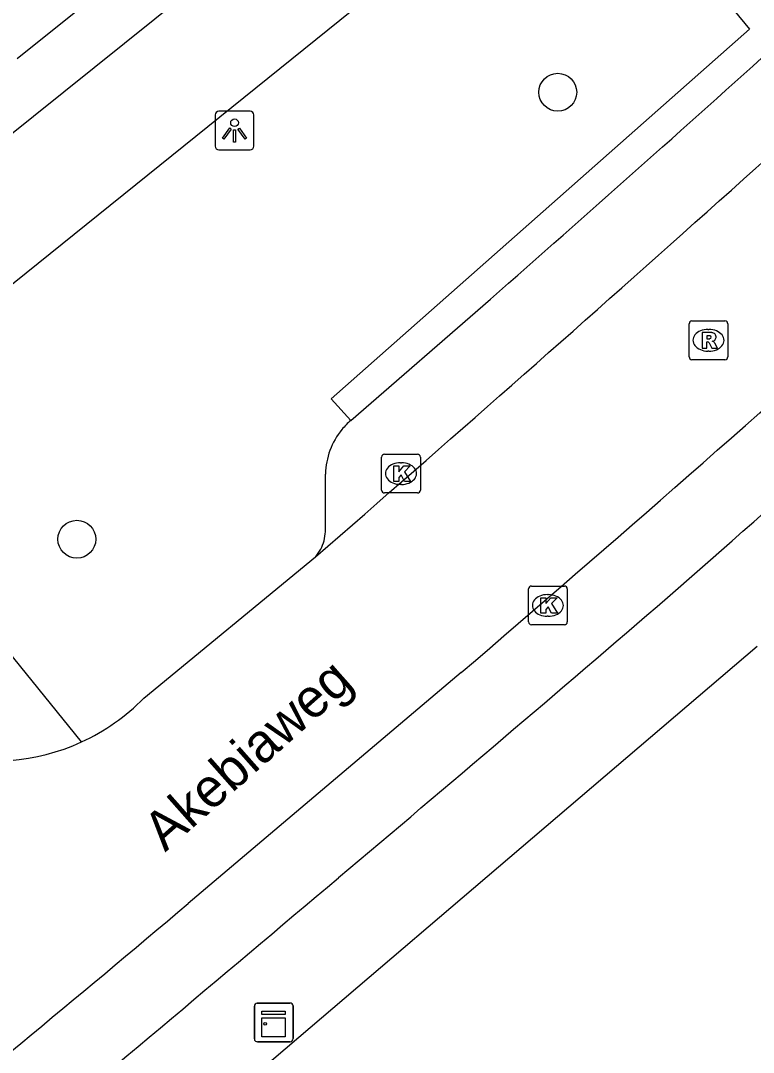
# Model space of a CAD drawing. Extents: x 162347 to 162868, y 381221 to 381813.
# Drawn here: x 162598.22 to 162617.14, y 381573.33 to 381599.97 of the extents above; entities that cross this region are included whole.
import ezdxf

# ---------------------------------------------------------------- set-up
doc = ezdxf.new("R2010")
doc.units = 0
for name, color, linetype in [('IMGEO_Boom', 7, 'Continuous'), ('IMGEO_Kast', 7, 'Continuous'), ('IMGEO_Kolk', 7, 'Continuous'), ('IMGEO_Lichtpunt', 7, 'Continuous'), ('IMGEO_Openbare_ruimte_label', 7, 'Continuous'), ('IMGEO_Pand', 7, 'Continuous'), ('IMGEO_Parkeervlak_open', 7, 'Continuous'), ('IMGEO_Rijbaan_lokaal_open', 7, 'Continuous'), ('IMGEO_Rioolput', 7, 'Continuous'), ('IMGEO_Voetpad_open', 7, 'Continuous')]:
    doc.layers.add(name, color=color, linetype=linetype)

msp = doc.modelspace()

# ---------------------------------------------------------------- linework, layer by layer
at = {"layer": 'IMGEO_Boom'}
for centre in [(162612.089, 381598.119), (162599.676, 381586.577)]:
    msp.add_circle(centre, 0.489, dxfattribs=at)
at = {"layer": 'IMGEO_Kast'}
for p, q in [((162604.257, 381573.675), (162604.257, 381574.516)), ((162604.257, 381574.516), (162604.257, 381573.675)), ((162604.332, 381574.6), (162605.173, 381574.6)), ((162605.173, 381574.6), (162604.332, 381574.6)), ((162605.257, 381574.525), (162605.257, 381573.684)), ((162605.257, 381573.684), (162605.257, 381574.525)), ((162605.182, 381573.6), (162604.341, 381573.6)), ((162604.341, 381573.6), (162605.182, 381573.6))]:
    msp.add_line(p, q, dxfattribs=at)
for points in [[(162604.452, 381574.39), (162605.052, 381574.39), (162605.052, 381574.305), (162604.452, 381574.305), (162604.452, 381574.39)], [(162604.452, 381574.215), (162605.052, 381574.215), (162605.052, 381573.726), (162604.452, 381573.726), (162604.452, 381574.215)]]:
    msp.add_lwpolyline(points, dxfattribs=at)
msp.add_circle((162604.536, 381574.064), 0.0377, dxfattribs=at)
for centre, start, end in [((162604.335, 381574.522), 92.4484, 184.2845), ((162604.335, 381574.522), 92.4484, 184.2845), ((162605.179, 381574.522), 2.4484, 94.2845), ((162605.179, 381574.522), 2.4484, 94.2845), ((162604.335, 381573.678), 182.4484, 274.2845), ((162604.335, 381573.678), 182.4484, 274.2845), ((162605.179, 381573.678), 272.4484, 4.2845), ((162605.179, 381573.678), 272.4484, 4.2845)]:
    msp.add_arc(centre, 0.0779, start, end, dxfattribs=at)
at = {"layer": 'IMGEO_Kolk'}
for p, q in [((162607.541, 381587.846), (162607.541, 381588.698)), ((162607.616, 381588.772), (162608.468, 381588.772)), ((162608.542, 381588.698), (162608.542, 381587.846)), ((162608.029, 381588.552), (162608.054, 381588.552)), ((162608.468, 381587.772), (162607.616, 381587.772)), ((162608.052, 381587.992), (162608.027, 381587.992)), ((162611.409, 381585.367), (162612.261, 381585.367)), ((162611.334, 381584.441), (162611.334, 381585.293)), ((162611.822, 381585.147), (162611.847, 381585.147)), ((162612.335, 381585.293), (162612.335, 381584.441)), ((162611.845, 381584.587), (162611.82, 381584.587)), ((162612.261, 381584.367), (162611.409, 381584.367))]:
    msp.add_line(p, q, dxfattribs=at)
for points in [[(162607.541, 381587.846), (162607.541, 381588.698)], [(162607.616, 381588.772), (162608.468, 381588.772)], [(162608.542, 381588.698), (162608.542, 381587.846)], [(162607.862, 381588.472), (162607.985, 381588.472), (162607.985, 381588.321), (162608.115, 381588.472), (162608.279, 381588.472), (162608.133, 381588.321), (162608.286, 381588.072), (162608.134, 381588.072), (162608.049, 381588.236), (162607.985, 381588.169), (162607.985, 381588.072), (162607.862, 381588.072), (162607.862, 381588.472)], [(162608.468, 381587.772), (162607.616, 381587.772)], [(162611.409, 381585.367), (162612.261, 381585.367)], [(162611.334, 381584.441), (162611.334, 381585.293)], [(162612.335, 381585.293), (162612.335, 381584.441)], [(162611.655, 381585.067), (162611.778, 381585.067), (162611.778, 381584.916), (162611.908, 381585.067), (162612.072, 381585.067), (162611.926, 381584.916), (162612.079, 381584.667), (162611.927, 381584.667), (162611.842, 381584.831), (162611.778, 381584.764), (162611.778, 381584.667), (162611.655, 381584.667), (162611.655, 381585.067)], [(162612.261, 381584.367), (162611.409, 381584.367)]]:
    msp.add_lwpolyline(points, dxfattribs=at)
for centre, start, end in [((162607.618, 381588.696), 91.552, 178.448), ((162607.618, 381588.696), 91.552, 178.448), ((162608.466, 381588.696), 1.552, 88.448), ((162608.466, 381588.696), 1.552, 88.448), ((162607.618, 381587.848), 181.552, 268.448), ((162607.618, 381587.848), 181.552, 268.448), ((162608.466, 381587.848), 271.552, 358.448), ((162608.466, 381587.848), 271.552, 358.448), ((162611.411, 381585.291), 91.552, 178.448), ((162611.411, 381585.291), 91.552, 178.448), ((162612.259, 381585.291), 1.552, 88.448), ((162612.259, 381585.291), 1.552, 88.448), ((162611.411, 381584.443), 181.552, 268.448), ((162611.411, 381584.443), 181.552, 268.448), ((162612.259, 381584.443), 271.552, 358.448), ((162612.259, 381584.443), 271.552, 358.448)]:
    msp.add_arc(centre, 0.0765, start, end, dxfattribs=at)
for centre, major_axis, ratio, start_param, end_param in [((162608.028, 381588.272), (-0.387, 0.002), 0.722429, 4.712389, 7.853982), ((162608.053, 381588.272), (-0.39, 0.002), 0.717154, 1.570796, 4.712389), ((162611.821, 381584.867), (-0.387, 0.002), 0.722429, 4.712389, 7.853982), ((162611.846, 381584.867), (-0.39, 0.002), 0.717154, 1.570796, 4.712389)]:
    msp.add_ellipse(centre, major_axis=major_axis, ratio=ratio, start_param=start_param, end_param=end_param, dxfattribs=at)
at = {"layer": 'IMGEO_Lichtpunt'}
for p, q in [((162604.149, 381597.628), (162603.341, 381597.628)), ((162604.149, 381597.628), (162603.341, 381597.628)), ((162603.247, 381597.533), (162603.247, 381596.726)), ((162603.247, 381597.533), (162603.247, 381596.726)), ((162604.243, 381596.726), (162604.243, 381597.533)), ((162604.243, 381596.726), (162604.243, 381597.533)), ((162603.341, 381596.632), (162604.149, 381596.632)), ((162603.341, 381596.632), (162604.149, 381596.632))]:
    msp.add_line(p, q, dxfattribs=at)
for points in [[(162603.621, 381597.197), (162603.66, 381597.169), (162603.472, 381596.907), (162603.434, 381596.934), (162603.621, 381597.197)], [(162603.723, 381597.149), (162603.77, 381597.149), (162603.77, 381596.827), (162603.723, 381596.827), (162603.723, 381597.149)], [(162603.833, 381597.169), (162603.871, 381597.196), (162604.058, 381596.934), (162604.019, 381596.906), (162603.833, 381597.169)]]:
    msp.add_lwpolyline(points, dxfattribs=at)
msp.add_circle((162603.746, 381597.331), 0.0994, dxfattribs=at)
for centre, start, end in [((162603.341, 381597.533), 90, 180), ((162603.341, 381597.533), 90, 180), ((162604.149, 381597.533), 0, 90), ((162604.149, 381597.533), 0, 90), ((162603.341, 381596.726), 180, 270), ((162603.341, 381596.726), 180, 270), ((162604.149, 381596.726), 270, 0), ((162604.149, 381596.726), 270, 360)]:
    msp.add_arc(centre, 0.0946, start, end, dxfattribs=at)
at = {"layer": 'IMGEO_Pand'}
msp.add_lwpolyline([(162598.133, 381598.994), (162603.15, 381603.02)], dxfattribs=at)
at = {"layer": 'IMGEO_Parkeervlak_open'}
msp.add_lwpolyline([(162606.091, 381586.771), (162606.095, 381588.261)], dxfattribs=at)
for centre, radius, start, end in [((162607.879, 381588.314), 1.747, 130.3263, 141.1491), ((162607.956, 381588.228), 1.862, 140.5909, 178.9871), ((162605.031, 381586.812), 1.061, 332.3969, 357.8036), ((162605.025, 381586.813), 1.067, 319.3854, 332.4487)]:
    msp.add_arc(centre, radius, start, end, dxfattribs=at)
at = {"layer": 'IMGEO_Rijbaan_lokaal_open'}
for points in [[(162601.403, 381582.472), (162605.835, 381586.119)], [(162609.593, 381583.132), (162602.55, 381577.172)]]:
    msp.add_lwpolyline(points, dxfattribs=at)
for centre, radius, start, end in [((161942.339, 382348.939), 1011, 311.016557, 312.544247), ((162205.379, 382055.51), 621.715, 310.553643, 311.98853), ((162597.542, 381586.26), 5.41, 214.8847, 294.6181), ((162597.556, 381586.238), 5.384, 294.5799, 315.6143), ((162306.96, 381926.435), 457.557, 308.83123, 310.24208)]:
    msp.add_arc(centre, radius, start, end, dxfattribs=at)
at = {"layer": 'IMGEO_Rioolput'}
for p, q in [((162615.479, 381591.288), (162615.479, 381592.14)), ((162615.554, 381592.214), (162616.406, 381592.214)), ((162616.48, 381592.14), (162616.48, 381591.288)), ((162615.967, 381591.994), (162615.992, 381591.994)), ((162615.99, 381591.434), (162615.965, 381591.434)), ((162616.406, 381591.214), (162615.554, 381591.214))]:
    msp.add_line(p, q, dxfattribs=at)
for points in [[(162615.479, 381591.288), (162615.479, 381592.14)], [(162615.554, 381592.214), (162616.406, 381592.214)], [(162616.48, 381592.14), (162616.48, 381591.288)], [(162616.068, 381591.912), (162615.816, 381591.914), (162615.816, 381591.514)], [(162615.994, 381591.833), (162615.94, 381591.833), (162615.94, 381591.752)], [(162615.94, 381591.752), (162615.992, 381591.752)], [(162615.816, 381591.514), (162615.94, 381591.514), (162615.94, 381591.676), (162615.951, 381591.676)], [(162615.998, 381591.647), (162616.069, 381591.514), (162616.209, 381591.514), (162616.144, 381591.64)], [(162616.406, 381591.214), (162615.554, 381591.214)]]:
    msp.add_lwpolyline(points, dxfattribs=at)
for centre, radius, start, end in [((162615.556, 381592.138), 0.0765, 91.552, 178.448), ((162615.556, 381592.138), 0.0765, 91.552, 178.448), ((162616.404, 381592.138), 0.0765, 1.552, 88.448), ((162616.404, 381592.138), 0.0765, 1.552, 88.448), ((162615.976, 381591.941), 0.19, 274.7715, 282.9687), ((162616, 381591.737), 0.0964, 77.0061, 93.1865), ((162616.014, 381591.794), 0.0378, 276.6634, 79.6772), ((162616.067, 381591.802), 0.109, 350.3612, 89.416), ((162616.065, 381591.802), 0.112, 277.5842, 350.9817), ((162615.95, 381591.623), 0.0533, 26.0293, 88.6989), ((162616.049, 381591.587), 0.108, 29.5134, 73.7905), ((162615.556, 381591.29), 0.0765, 181.552, 268.448), ((162615.556, 381591.29), 0.0765, 181.552, 268.448), ((162616.404, 381591.29), 0.0765, 271.552, 358.448), ((162616.404, 381591.29), 0.0765, 271.552, 358.448)]:
    msp.add_arc(centre, radius, start, end, dxfattribs=at)
for centre, major_axis, ratio, start_param, end_param in [((162615.966, 381591.714), (-0.387, 0.002), 0.722429, 4.712389, 7.853982), ((162615.991, 381591.714), (-0.39, 0.002), 0.717154, 1.570796, 4.712389)]:
    msp.add_ellipse(centre, major_axis=major_axis, ratio=ratio, start_param=start_param, end_param=end_param, dxfattribs=at)
at = {"layer": 'IMGEO_Voetpad_open'}
for points in [[(162629.662, 381622.463), (162593.892, 381593.755)], [(162596.806, 381592.212), (162612.702, 381605.014), (162617.041, 381599.75), (162606.244, 381590.2), (162606.748, 381589.646)], [(162606.748, 381589.646), (162610.351, 381592.776)], [(162599.795, 381581.342), (162596.143, 381585.85)], [(162599.604, 381568.769), (162617.236, 381583.812)]]:
    msp.add_lwpolyline(points, dxfattribs=at)
for centre, radius, start, end in [((162012.532, 382272.566), 905.263, 311.328974, 312.594769), ((162286.159, 381962.013), 500.168, 311.09424, 312.45287), ((161962.733, 382342.089), 999.211, 310.105994, 310.745584), ((161624.099, 382738.088), 1520.247, 309.799914, 310.253015)]:
    msp.add_arc(centre, radius, start, end, dxfattribs=at)

# ---------------------------------------------------------------- texts
at = {"layer": 'IMGEO_Openbare_ruimte_label'}
msp.add_text('Akebiaweg', height=1, rotation=41.5146, dxfattribs=at).set_placement((162601.955, 381578.486))

doc.saveas('drawing.dxf')
